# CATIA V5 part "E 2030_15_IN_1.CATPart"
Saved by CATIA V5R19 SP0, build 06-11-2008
Material "Plastic": density 1200 kg/m3, Young's modulus 2.2e+09 Pa, Poisson ratio 0.38, thermal expansion 6.84e-05 1/K
Bounding box of the stored display mesh (mm): x -7.55 to 7.55, y -7.54 to 7.54, z -2 to 0
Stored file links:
  G:\UTB\Kombinované\Bakalářská práce\Catia\FORMA\E 2030_15_IN_1.CATPart
  D:\Aplikace\CATIA\Nová složka\win_b64\startup\materials\Catalog.CATMaterial
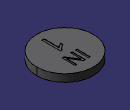
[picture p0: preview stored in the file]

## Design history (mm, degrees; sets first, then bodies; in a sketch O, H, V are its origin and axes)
Body1 "E 2030_15_IN_1-8" (main body)
  Solid1: solid without history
